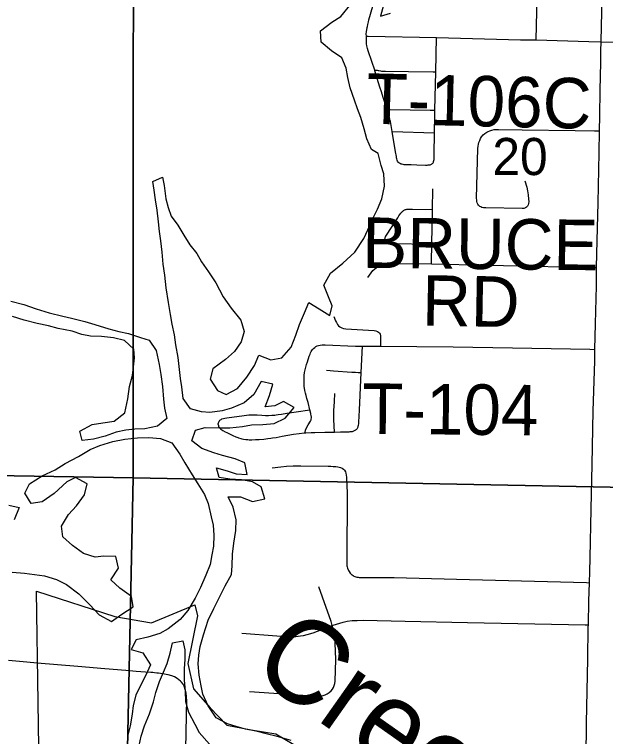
# Model space of a CAD drawing. Extents: x -38.1 to 35.9, y -2.7 to 28.5.
# Drawn here: x 22.949 to 23.615, y 16.713 to 17.526 of the extents above; entities that cross this region are included whole.
import ezdxf

# ---------------------------------------------------------------- set-up
doc = ezdxf.new("R2010")
doc.units = 0
for name, color, linetype in [('GM_X_Interchange_Ramps', 7, 'Continuous'), ('GM_X_Interstate_Shield', 7, 'Continuous'), ('GM_X_Major_River_Text', 7, 'Continuous'), ('GM_X_Minor_Lake', 7, 'Continuous'), ('GM_X_Minor_River', 7, 'Continuous'), ('GM_X_Township_Road_Text', 7, 'Continuous'), ('GM_X_US_Route', 7, 'Continuous')]:
    doc.layers.add(name, color=color, linetype=linetype)

msp = doc.modelspace()

# ---------------------------------------------------------------- linework, layer by layer
at = {"layer": 'GM_X_Interchange_Ramps'}
for points in [[(23.60965, 17.48482), (23.60987, 17.49479), (23.69774, 17.49333)], [(23.59283, 16.68843), (23.59352, 16.7282), (23.59506, 16.79963), (23.59541, 16.83568), (23.59547, 16.83847), (23.59611, 16.86551), (23.59662, 16.88578), (23.59695, 16.89844), (23.59748, 16.91396), (23.59869, 16.96862), (23.59964, 17.01895), (23.60104, 17.07922), (23.60258, 17.13512), (23.60285, 17.14857), (23.60342, 17.17737), (23.60449, 17.22022), (23.60483, 17.24056), (23.60533, 17.27118), (23.60642, 17.31342), (23.6077, 17.36995), (23.60808, 17.39466), (23.60834, 17.41159), (23.60873, 17.44016), (23.60937, 17.47185), (23.60965, 17.48482)], [(23.02063, 16.7914), (22.97473, 16.79535), (22.96297, 16.79619), (22.94258, 16.7981)], [(23.14209, 16.70252), (23.1424, 16.71353), (23.14305, 16.74017), (23.14325, 16.75191), (23.14301, 16.75759), (23.14259, 16.76134), (23.14155, 16.76566), (23.14026, 16.76927), (23.13905, 16.77158), (23.13747, 16.77369), (23.13608, 16.7751), (23.13435, 16.77647), (23.13229, 16.77801), (23.1295, 16.77964), (23.12653, 16.78086), (23.12231, 16.78204), (23.12005, 16.78257), (23.11808, 16.78289), (23.11577, 16.7833), (23.11363, 16.78363), (23.1115, 16.78387), (23.10936, 16.78412), (23.10689, 16.78435), (23.10502, 16.78453), (23.10259, 16.78479), (23.09661, 16.78518), (23.08611, 16.78595), (23.07467, 16.78679), (23.05096, 16.78885), (23.02063, 16.7914)]]:
    msp.add_lwpolyline(points, dxfattribs=at)
at = {"layer": 'GM_X_Interstate_Shield'}
for points in [[(23.35134, 17.37349), (23.34601, 17.38579), (23.34292, 17.39688), (23.33912, 17.40952), (23.33561, 17.41948), (23.3321, 17.42907), (23.32719, 17.44288), (23.3245, 17.45472), (23.32291, 17.46501), (23.31794, 17.47692), (23.3064, 17.48485), (23.29453, 17.4943), (23.29377, 17.50722), (23.3066, 17.5171), (23.31666, 17.52326), (23.32848, 17.53771)], [(23.3649, 17.53627), (23.3615, 17.52385), (23.3726, 17.52694)], [(23.17777, 17.10236), (23.18754, 17.09758), (23.20023, 17.10451), (23.21077, 17.11718), (23.21942, 17.13027), (23.22425, 17.14193), (23.2378, 17.13669), (23.25039, 17.13906), (23.26092, 17.15097), (23.26616, 17.16452), (23.27023, 17.17658), (23.27584, 17.18974), (23.28066, 17.2014), (23.29228, 17.1943), (23.30427, 17.18681), (23.30679, 17.19739), (23.30284, 17.20773), (23.29743, 17.22076), (23.30495, 17.23426), (23.31889, 17.24571), (23.33246, 17.25793), (23.34268, 17.27327), (23.34708, 17.28304), (23.35189, 17.29432), (23.35785, 17.30633), (23.36305, 17.31798), (23.36603, 17.33234), (23.3652, 17.34603), (23.362, 17.35559), (23.35888, 17.36895), (23.35134, 17.37349)], [(23.15729, 16.78162), (23.15606, 16.79456), (23.15666, 16.80403), (23.1584, 16.81387), (23.16211, 16.82707), (23.16742, 16.84366), (23.17379, 16.8568), (23.18055, 16.87032), (23.18652, 16.88233), (23.19365, 16.89508), (23.19425, 16.90494), (23.19492, 16.91783), (23.19633, 16.93033), (23.19856, 16.94471), (23.19882, 16.95647), (23.19534, 16.97097), (23.1899, 16.98249), (23.20358, 16.98256), (23.21714, 16.97731), (23.23127, 16.98041), (23.22701, 16.9938), (23.21726, 16.99933), (23.20477, 17.00151), (23.19187, 17.00257), (23.17976, 17.00436), (23.17658, 17.01506), (23.18866, 17.01175), (23.19884, 17.00848), (23.21137, 17.00782), (23.20862, 17.02079), (23.1977, 17.02521), (23.18335, 17.02896), (23.17354, 17.03222), (23.16035, 17.03707), (23.14877, 17.04569), (23.15322, 17.05773), (23.16392, 17.06053), (23.18024, 17.06016), (23.19165, 17.06028), (23.20612, 17.06185), (23.21603, 17.06353), (23.22896, 17.06399), (23.24152, 17.06523), (23.25419, 17.07101), (23.26434, 17.08293), (23.25233, 17.08966), (23.24234, 17.08495), (23.23168, 17.08367), (23.23652, 17.09647), (23.24023, 17.1093), (23.227, 17.11225), (23.21869, 17.09764), (23.20785, 17.08839), (23.19366, 17.08226), (23.18296, 17.07946), (23.16923, 17.07749), (23.15975, 17.07809), (23.14729, 17.08141), (23.13919, 17.09336), (23.13759, 17.10631), (23.13628, 17.11583), (23.13468, 17.12915), (23.13339, 17.13943), (23.13105, 17.15353), (23.1294, 17.16496), (23.12663, 17.17679), (23.12497, 17.18784), (23.12261, 17.20118), (23.11995, 17.21795), (23.11836, 17.23203), (23.11675, 17.2446), (23.11552, 17.25791), (23.11391, 17.27085), (23.11262, 17.28114), (23.11135, 17.29218), (23.10974, 17.30512), (23.10811, 17.31693), (23.10645, 17.32797), (23.10515, 17.3375), (23.1159, 17.34257), (23.11796, 17.33303), (23.11953, 17.31819), (23.12235, 17.30825), (23.12555, 17.29869), (23.1333, 17.28826), (23.13989, 17.2771), (23.14687, 17.26632), (23.15463, 17.25665), (23.15973, 17.24704), (23.16784, 17.23585), (23.17592, 17.22352), (23.18431, 17.20776), (23.19314, 17.19503), (23.20423, 17.18149), (23.20774, 17.1685), (23.20445, 17.15719), (23.19698, 17.14597), (23.1869, 17.13708), (23.17262, 17.12678), (23.16969, 17.11507), (23.17777, 17.10236)], [(22.94523, 17.20289), (22.95958, 17.19915), (22.97353, 17.19428), (22.98824, 17.18978), (23.00374, 17.18601), (23.01356, 17.18351), (23.02829, 17.17977), (23.03962, 17.17647), (23.05546, 17.17156), (23.0668, 17.16865), (23.07776, 17.1665), (23.09096, 17.16203), (23.10077, 17.15877), (23.10887, 17.1472), (23.11232, 17.13155), (23.11396, 17.12013), (23.11594, 17.10679), (23.11714, 17.09234), (23.11806, 17.08245), (23.12083, 17.07061), (23.11038, 17.06212), (23.09588, 17.05903), (23.08485, 17.05852), (23.07457, 17.05761), (23.06388, 17.05519), (23.05124, 17.05092), (23.03825, 17.04742), (23.0253, 17.04581), (23.02287, 17.05649), (23.03672, 17.06378), (23.04854, 17.06579), (23.0615, 17.06778), (23.07348, 17.077), (23.07688, 17.09287), (23.07871, 17.10687), (23.08202, 17.11895), (23.08338, 17.12879), (23.08437, 17.13902), (23.08345, 17.14891), (23.07303, 17.15864), (23.06056, 17.16157), (23.04729, 17.16301), (23.03476, 17.16329), (23.02493, 17.16541), (23.014, 17.16908), (22.99849, 17.17208), (22.98753, 17.17499), (22.97467, 17.17755), (22.95994, 17.1813), (22.94711, 17.18538)], [(22.94676, 16.8976), (22.96041, 16.89653), (22.97177, 16.89514), (22.98313, 16.89337), (22.99672, 16.88927), (23.00761, 16.88371), (23.02181, 16.87314), (23.03407, 16.86071), (23.04446, 16.84947), (23.05835, 16.84194), (23.06993, 16.85041), (23.08303, 16.85847), (23.08102, 16.87028), (23.06793, 16.87969), (23.05788, 16.88903), (23.06653, 16.90212), (23.06341, 16.91548), (23.04974, 16.91579), (23.04021, 16.91449), (23.02701, 16.91858), (23.01467, 16.92759), (23.00349, 16.93733), (23.00225, 16.94951), (23.01014, 16.96262), (23.01909, 16.97229), (23.02811, 16.98462), (23.03104, 16.99708), (23.01791, 17.00421), (23.0083, 16.99949), (22.99395, 16.98614), (22.98044, 16.97696), (22.96786, 16.97496), (22.9609, 16.98651), (22.96608, 16.99702), (22.98034, 17.00619), (22.99493, 17.01308), (23.00648, 17.02003), (23.02148, 17.02805), (23.03457, 17.03573), (23.04531, 17.04042), (23.05984, 17.04465), (23.07358, 17.04738), (23.08767, 17.04896), (23.1006, 17.04943), (23.11349, 17.048), (23.1263, 17.04316), (23.13551, 17.03042), (23.14099, 17.0208), (23.14943, 17.00732), (23.15566, 16.99731), (23.16337, 16.98499), (23.16732, 16.97503), (23.17079, 16.96014), (23.17285, 16.9506), (23.17374, 16.93919), (23.17347, 16.92705), (23.17135, 16.91722), (23.16958, 16.90625), (23.16475, 16.89421), (23.15874, 16.8803), (23.15278, 16.86829), (23.14449, 16.85443), (23.1359, 16.84437), (23.12238, 16.83404), (23.11276, 16.82856), (23.09936, 16.82431)], [(22.94275, 16.97324), (22.95446, 16.97032), (22.94884, 16.95678)], [(23.09936, 16.82431), (23.08638, 16.82157), (23.08044, 16.81069), (23.09365, 16.80698), (23.10247, 16.79349), (23.09727, 16.78183), (23.09092, 16.76945), (23.08575, 16.75931), (23.08283, 16.74761), (23.08185, 16.73776), (23.07965, 16.72452), (23.07634, 16.71245)], [(23.08855, 16.69736), (23.09193, 16.71285), (23.09561, 16.72454), (23.10123, 16.73808), (23.10571, 16.75165), (23.10823, 16.76222), (23.11269, 16.77465), (23.1171, 16.78518), (23.12112, 16.79497), (23.12441, 16.80628), (23.12733, 16.81799), (23.13879, 16.82038), (23.14122, 16.81008), (23.14099, 16.79983), (23.14036, 16.78884), (23.14045, 16.77593), (23.14132, 16.76376), (23.14181, 16.75198), (23.14535, 16.74013), (23.15227, 16.72668), (23.15737, 16.71707), (23.16885, 16.7039)], [(23.26089, 16.70828), (23.24504, 16.71281), (23.23256, 16.71575), (23.22085, 16.71867), (23.2095, 16.72083), (23.19893, 16.72373), (23.18913, 16.72699), (23.17636, 16.73373), (23.16716, 16.74723), (23.16138, 16.76026), (23.15931, 16.7698), (23.15729, 16.78162)]]:
    msp.add_lwpolyline(points, dxfattribs=at)
at = {"layer": 'GM_X_Major_River_Text'}
for p, q in [((23.53667, 17.49702), (23.53798, 17.55109)), ((23.42367, 17.46089), (23.42441, 17.4998)), ((23.42277, 17.41801), (23.42367, 17.46089)), ((23.37454, 17.39378), (23.42232, 17.3924))]:
    msp.add_line(p, q, dxfattribs=at)
for points in [[(23.60987, 17.49479), (23.61031, 17.51242), (23.62298, 18.02747)], [(23.34547, 17.50117), (23.34544, 17.50361), (23.34577, 17.50657), (23.346, 17.50822), (23.34641, 17.51087), (23.34661, 17.51201), (23.34715, 17.5145), (23.34781, 17.51737), (23.34836, 17.51958), (23.35794, 17.55332)], [(23.35488, 17.46301), (23.3515, 17.47266), (23.34767, 17.4848), (23.34683, 17.4875), (23.34613, 17.49042), (23.34578, 17.49261), (23.34552, 17.49544), (23.34547, 17.50117)], [(23.34547, 17.50117), (23.34754, 17.50113), (23.42441, 17.4998)], [(23.42441, 17.4998), (23.51894, 17.49727), (23.53667, 17.49702)], [(23.53667, 17.49702), (23.59615, 17.49519), (23.60987, 17.49479)], [(23.35488, 17.46301), (23.35571, 17.46304), (23.35712, 17.46298), (23.35774, 17.46288), (23.35888, 17.46261), (23.35958, 17.46243), (23.36149, 17.46206), (23.36267, 17.46191), (23.36405, 17.46179), (23.36706, 17.4617), (23.39304, 17.46156), (23.42065, 17.46099), (23.42367, 17.46089)], [(23.36902, 17.41835), (23.36454, 17.4321), (23.36249, 17.43838), (23.36082, 17.44364), (23.35514, 17.46221), (23.35488, 17.46301)], [(23.36902, 17.41835), (23.37217, 17.41846), (23.41748, 17.41806), (23.42277, 17.41801)], [(23.37454, 17.39378), (23.37301, 17.40271), (23.37256, 17.40518), (23.37237, 17.40619), (23.37206, 17.40768), (23.37157, 17.40983), (23.37115, 17.41147), (23.36993, 17.41557), (23.36902, 17.41835)], [(23.42232, 17.3924), (23.42265, 17.41209), (23.42277, 17.41801)], [(23.41937, 17.35741), (23.41852, 17.35684), (23.41787, 17.35646), (23.41694, 17.35614), (23.41577, 17.35591), (23.41471, 17.35581), (23.41346, 17.35575), (23.41213, 17.35573), (23.40246, 17.35599), (23.39577, 17.35617), (23.39091, 17.35632), (23.38866, 17.35645), (23.38791, 17.3565), (23.38684, 17.35662), (23.38539, 17.35693), (23.38477, 17.35716), (23.38397, 17.3575), (23.38261, 17.35831), (23.38206, 17.35877), (23.38148, 17.35941), (23.3807, 17.36059), (23.38035, 17.36142), (23.37984, 17.36314), (23.37958, 17.36427), (23.37931, 17.36553), (23.37828, 17.37083), (23.37454, 17.39378)], [(23.52386, 17.33828), (23.52602, 17.33101), (23.52692, 17.32719), (23.52775, 17.32248), (23.52825, 17.31768), (23.52833, 17.31508), (23.52808, 17.31269), (23.52755, 17.31116), (23.52681, 17.30976), (23.52587, 17.30865), (23.52456, 17.30792), (23.52266, 17.30733), (23.52097, 17.30704), (23.47989, 17.30785), (23.47753, 17.30804), (23.47556, 17.30837), (23.4744, 17.30886), (23.47336, 17.30942), (23.47234, 17.31025), (23.47163, 17.31108), (23.47099, 17.31206), (23.47033, 17.31341), (23.46992, 17.3151), (23.46971, 17.3167), (23.4696, 17.31874), (23.4711, 17.3747), (23.47133, 17.37731), (23.47182, 17.37969), (23.47222, 17.38145), (23.47308, 17.38384), (23.47411, 17.38603), (23.47526, 17.38787), (23.47709, 17.38998), (23.479, 17.39157), (23.48105, 17.39296), (23.48278, 17.39384), (23.48442, 17.39458), (23.48678, 17.39537), (23.48944, 17.39594), (23.49161, 17.39619), (23.49412, 17.39628), (23.52087, 17.39582), (23.58056, 17.3951), (23.60232, 17.39476), (23.60808, 17.39466)], [(23.41937, 17.35741), (23.41996, 17.35796), (23.4206, 17.35875), (23.42095, 17.35932), (23.42123, 17.35995), (23.42153, 17.36115), (23.4217, 17.36252), (23.42175, 17.36326), (23.42182, 17.36467), (23.42186, 17.36583), (23.42191, 17.36799), (23.42232, 17.3924)], [(23.41928, 17.2668), (23.41994, 17.30609), (23.4205, 17.32922)], [(23.41928, 17.2668), (23.37397, 17.26729), (23.37255, 17.26736), (23.37142, 17.26746), (23.37063, 17.26758), (23.36985, 17.26772), (23.3691, 17.26794), (23.36823, 17.26835), (23.36751, 17.26889), (23.36697, 17.26949), (23.36651, 17.27044), (23.36623, 17.27172), (23.36625, 17.27285), (23.36648, 17.27392), (23.36721, 17.27545), (23.36756, 17.27605), (23.38074, 17.29673), (23.38204, 17.29872), (23.3833, 17.30057), (23.38424, 17.30181), (23.38491, 17.30263), (23.3855, 17.30331), (23.38653, 17.30429), (23.38733, 17.30492), (23.38792, 17.30532), (23.3886, 17.30569), (23.38939, 17.30596), (23.39024, 17.30615), (23.39113, 17.30626), (23.39221, 17.30636), (23.39341, 17.30641), (23.39758, 17.30643), (23.41994, 17.30609)], [(23.41897, 17.24475), (23.41901, 17.24736), (23.41928, 17.2668)], [(23.34721, 17.2296), (23.35282, 17.23721), (23.35461, 17.239), (23.35673, 17.24059), (23.35889, 17.24196), (23.36134, 17.24295), (23.36415, 17.24394), (23.3676, 17.24452), (23.37229, 17.24485), (23.38011, 17.2452), (23.41897, 17.24475)], [(23.41897, 17.24475), (23.43302, 17.24459), (23.56672, 17.24151), (23.60027, 17.24067), (23.60483, 17.24056)], [(23.30874, 17.18551), (23.31081, 17.18081), (23.31174, 17.1788), (23.31308, 17.1766), (23.31422, 17.17519), (23.31573, 17.17394), (23.31779, 17.17285), (23.3199, 17.17206), (23.32219, 17.17162), (23.35437, 17.16975), (23.35615, 17.16938), (23.35818, 17.16854), (23.35928, 17.16777), (23.36024, 17.16687), (23.3609, 17.16568), (23.36126, 17.16428), (23.36141, 17.1625), (23.36146, 17.15222)], [(23.1787, 17.06396), (23.17881, 17.06288), (23.17896, 17.06222), (23.17952, 17.06102), (23.17997, 17.0604), (23.18054, 17.05971), (23.18164, 17.05876), (23.18275, 17.05792), (23.18403, 17.05709), (23.18652, 17.05575), (23.1883, 17.05488), (23.19049, 17.05383), (23.19507, 17.05168), (23.19854, 17.05009), (23.2007, 17.04922), (23.20162, 17.0489), (23.20398, 17.04819), (23.20521, 17.04786), (23.20704, 17.04745), (23.20962, 17.04707), (23.21217, 17.04688), (23.21343, 17.04683), (23.21651, 17.04682), (23.2205, 17.04691), (23.22493, 17.0471), (23.22995, 17.04745), (23.23209, 17.04767), (23.23466, 17.048), (23.23776, 17.04845), (23.23964, 17.04875), (23.24374, 17.04948), (23.25061, 17.0508), (23.26344, 17.05315), (23.26972, 17.05395), (23.27553, 17.05447), (23.27652, 17.05454), (23.27748, 17.0546), (23.28348, 17.05483), (23.28731, 17.05492), (23.29876, 17.05515), (23.30953, 17.05536), (23.3165, 17.05553), (23.3241, 17.05574), (23.3262, 17.05583), (23.32718, 17.05589), (23.32877, 17.05604), (23.32985, 17.05621), (23.33066, 17.05641), (23.3315, 17.05671), (23.33223, 17.05703), (23.33356, 17.05789), (23.33418, 17.05842), (23.33466, 17.05887), (23.33507, 17.05936), (23.33546, 17.05988), (23.33594, 17.06072), (23.33621, 17.06141), (23.33643, 17.06212), (23.33667, 17.06332), (23.33684, 17.06466), (23.33702, 17.06647), (23.33782, 17.08022), (23.33974, 17.12253), (23.34107, 17.15204)], [(23.27652, 17.05454), (23.27666, 17.0559), (23.27679, 17.05695), (23.277, 17.05774), (23.27798, 17.06005), (23.27981, 17.06345), (23.28253, 17.06762), (23.28294, 17.06862), (23.28316, 17.06928), (23.28338, 17.0701), (23.28356, 17.07147), (23.28359, 17.07226), (23.28344, 17.07397), (23.28313, 17.07564), (23.28292, 17.07651), (23.28192, 17.08048), (23.27978, 17.08858), (23.27849, 17.09326), (23.27764, 17.09644), (23.27691, 17.09939), (23.27631, 17.10222), (23.27585, 17.10502), (23.27559, 17.1067), (23.2754, 17.10859), (23.27534, 17.11029), (23.27532, 17.11206), (23.27534, 17.11388), (23.2754, 17.11601), (23.27561, 17.11906), (23.276, 17.12247), (23.27661, 17.12564), (23.27728, 17.12856), (23.27812, 17.13155), (23.27904, 17.13447), (23.28122, 17.14105), (23.28201, 17.14323), (23.28255, 17.14451), (23.28337, 17.14611), (23.28398, 17.14714), (23.28493, 17.1485), (23.2859, 17.14966), (23.28727, 17.1508), (23.28862, 17.15175), (23.29015, 17.15245), (23.29171, 17.15302), (23.29355, 17.15344), (23.29586, 17.15371), (23.29891, 17.15373), (23.33318, 17.15227), (23.34107, 17.15204)], [(23.34107, 17.15204), (23.35184, 17.15212), (23.36146, 17.15222)], [(23.36146, 17.15222), (23.44334, 17.15153), (23.50988, 17.1503), (23.5972, 17.14868), (23.60285, 17.14857)], [(23.30073, 17.12513), (23.30484, 17.12474), (23.30854, 17.12444), (23.32903, 17.12301), (23.33334, 17.12276), (23.33621, 17.12263), (23.33864, 17.12255), (23.33974, 17.12253)], [(23.30953, 17.05536), (23.30896, 17.06964), (23.30882, 17.07424), (23.30877, 17.07665), (23.30886, 17.07997), (23.30907, 17.08426), (23.30947, 17.09), (23.31007, 17.09891)], [(23.1787, 17.06396), (23.17874, 17.06485), (23.17887, 17.06575), (23.17921, 17.06672), (23.17974, 17.06769), (23.18012, 17.06822), (23.18064, 17.0688), (23.18125, 17.06933), (23.1819, 17.06975), (23.18274, 17.07015), (23.18465, 17.07072), (23.18611, 17.07105), (23.18842, 17.07144), (23.2079, 17.07426), (23.21294, 17.07471), (23.21499, 17.0748), (23.21906, 17.07487), (23.22239, 17.07486), (23.22786, 17.07448), (23.23173, 17.07422), (23.23523, 17.07419), (23.23888, 17.07431), (23.24229, 17.07459), (23.24383, 17.07476), (23.24618, 17.07504), (23.24975, 17.07553), (23.25592, 17.07659), (23.26661, 17.07817), (23.28192, 17.08048)], [(23.23954, 17.01515), (23.24908, 17.01622), (23.2556, 17.01696), (23.26289, 17.01732), (23.27174, 17.01755), (23.30256, 17.01699), (23.30535, 17.01688), (23.30809, 17.01671), (23.31102, 17.01647), (23.31341, 17.01619), (23.31493, 17.0159), (23.31653, 17.0154), (23.31805, 17.01463), (23.31962, 17.01352), (23.32087, 17.01234), (23.32188, 17.01072), (23.3225, 17.009), (23.32291, 17.00673), (23.32312, 17.00471), (23.32399, 16.98609), (23.32398, 16.96495), (23.32348, 16.93387), (23.32341, 16.90776), (23.32343, 16.90627), (23.3236, 16.90483), (23.32381, 16.90351), (23.32422, 16.90199), (23.32484, 16.90043), (23.32537, 16.89936), (23.32597, 16.89829), (23.3271, 16.89673), (23.32784, 16.89591), (23.32862, 16.89522), (23.3294, 16.8946), (23.33064, 16.89386), (23.33154, 16.89333), (23.33249, 16.89287), (23.33364, 16.89246), (23.33475, 16.89214), (23.33607, 16.89193), (23.33744, 16.89179), (23.34005, 16.89169), (23.34618, 16.89167), (23.37664, 16.89181), (23.44686, 16.88986), (23.59348, 16.88587), (23.59662, 16.88578)], [(23.30704, 16.83747), (23.30581, 16.84213), (23.29615, 16.8694), (23.29195, 16.88122)], [(23.30704, 16.83747), (23.30821, 16.83791), (23.31938, 16.84138), (23.32402, 16.84235), (23.32966, 16.84308), (23.33528, 16.84343), (23.34197, 16.84353), (23.38917, 16.84252), (23.4594, 16.84108), (23.59203, 16.83854), (23.59547, 16.83847)], [(23.20531, 16.8291), (23.24457, 16.82592), (23.26017, 16.82505), (23.26599, 16.82537), (23.27117, 16.82587), (23.27462, 16.82636), (23.27897, 16.82751), (23.28548, 16.82935), (23.30704, 16.83747)], [(23.21373, 16.76316), (23.2849, 16.75849), (23.29378, 16.75853), (23.29691, 16.75888), (23.29913, 16.75956), (23.30129, 16.76061), (23.30369, 16.76228), (23.30566, 16.764), (23.3072, 16.76579), (23.30843, 16.76777), (23.30937, 16.77), (23.31007, 16.77245), (23.31046, 16.77504), (23.31119, 16.79944), (23.3105, 16.81755), (23.31003, 16.82276), (23.30937, 16.82728), (23.30867, 16.83121), (23.30704, 16.83747)]]:
    msp.add_lwpolyline(points, dxfattribs=at)
at = {"layer": 'GM_X_US_Route'}
for points in [[(23.0833, 18.00706), (23.08302, 17.00397), (21.98921, 17.02221), (22.01452, 18.02655)], [(24.12478, 17.98667), (24.09987, 16.98408), (23.08302, 17.00397), (23.0833, 18.00706)], [(21.98921, 17.02221), (23.08302, 17.00397), (23.0619, 15.99964), (21.96625, 16.01981)], [(23.08302, 17.00397), (24.09987, 16.98408), (24.07073, 15.97691), (23.0619, 15.99964)]]:
    msp.add_lwpolyline(points, close=True, dxfattribs=at)
msp.add_lwpolyline([(22.97781, 16.62546), (22.97399, 16.8762), (23.06234, 16.84764), (23.10339, 16.8405), (23.15248, 16.86102), (23.15515, 16.84853), (23.14444, 16.79498), (23.15069, 16.76643), (23.16943, 16.74501), (23.18817, 16.72538), (23.21583, 16.72003), (23.2435, 16.71556), (23.27384, 16.69772)], dxfattribs=at)

# ---------------------------------------------------------------- texts
at = {"layer": 'GM_X_Minor_Lake'}
for s, rotation, p in [('T-106C', 358.67307, (23.345, 17.40269)), ('BRUCE', 359.3838, (23.34055, 17.24043)), ('RD', 359.01089, (23.40784, 17.17539)), ('T-104', 359.43753, (23.34058, 17.0536))]:
    msp.add_text(s, height=0.056818, rotation=rotation, dxfattribs=at).set_placement(p)
at = {"layer": 'GM_X_Minor_River'}
msp.add_text('20', height=0.041856, rotation=0.00001, dxfattribs=at).set_placement((23.48738, 17.34477))
at = {"layer": 'GM_X_Township_Road_Text'}
msp.add_text('Creek', height=0.094683, rotation=324.81821, dxfattribs=at).set_placement((23.21261, 16.78534))

doc.saveas('drawing.dxf')
